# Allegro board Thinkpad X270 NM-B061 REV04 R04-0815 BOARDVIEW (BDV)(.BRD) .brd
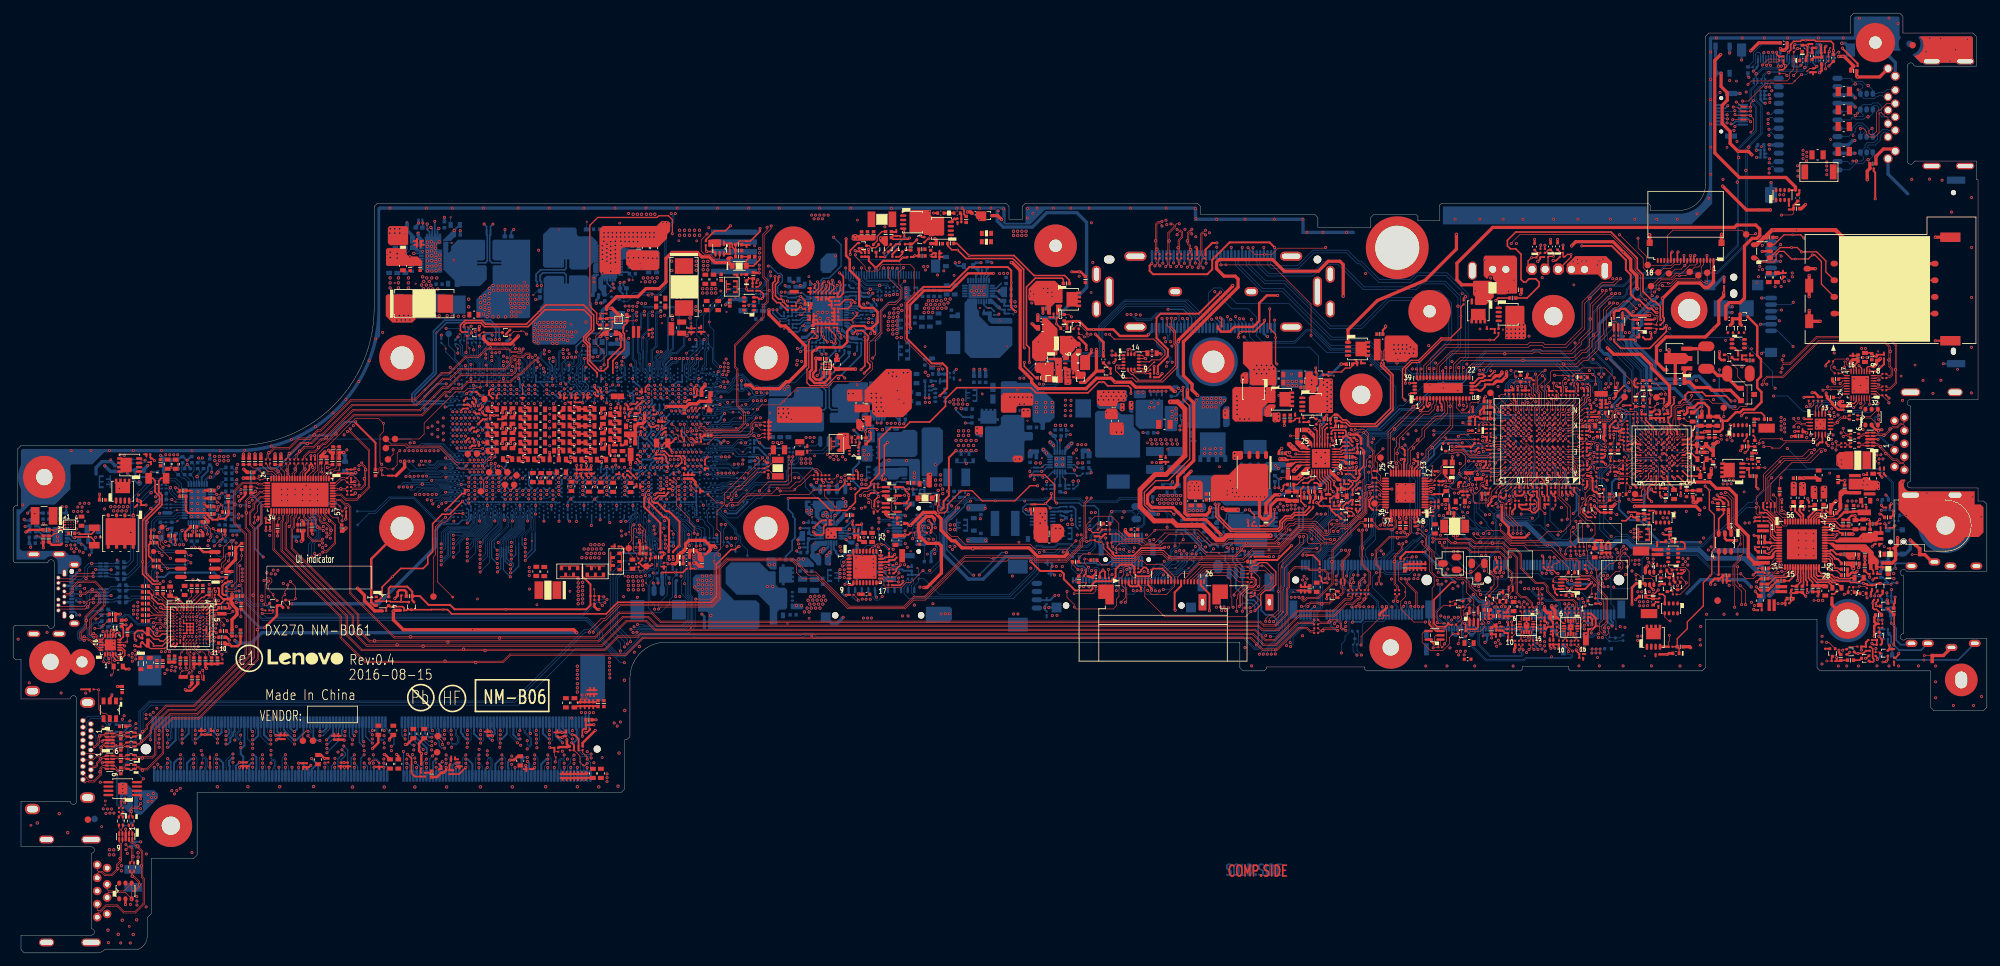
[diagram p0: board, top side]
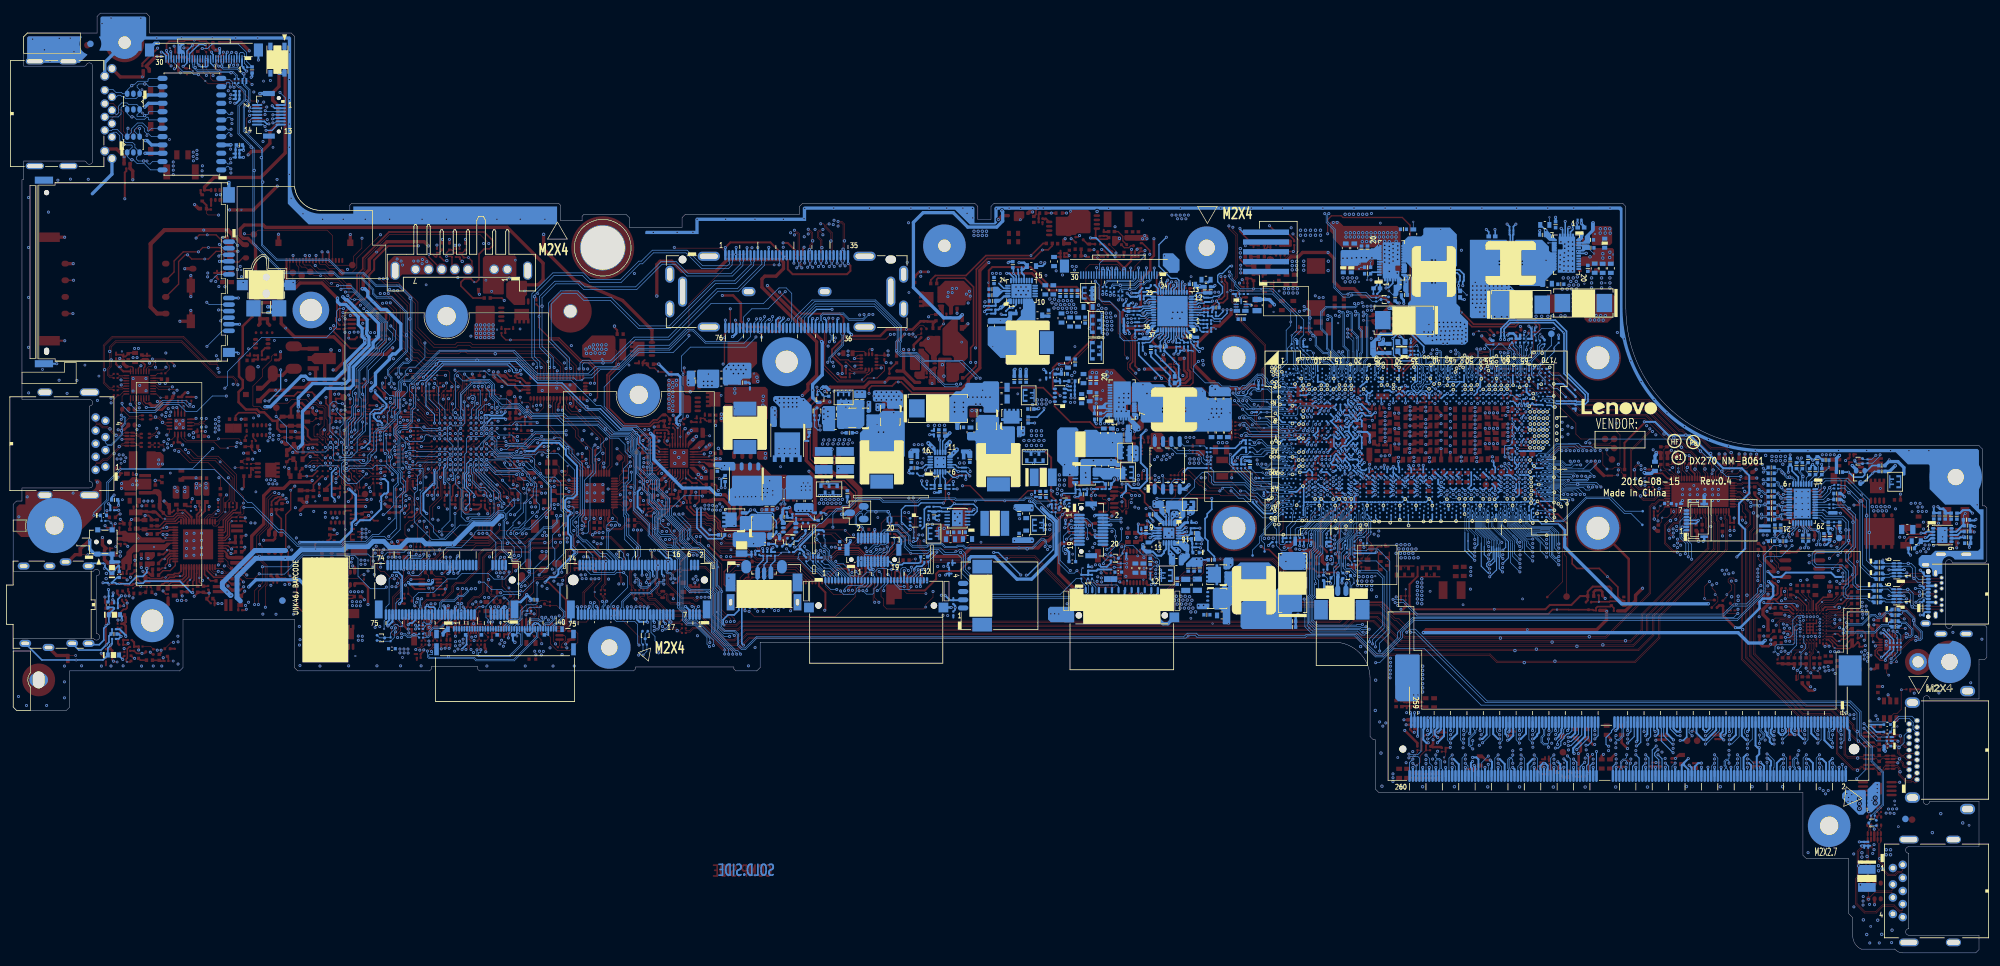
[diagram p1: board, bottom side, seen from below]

Outline 300.95 x 143.41 mm; copper layers: TOP, GND1, IN1, VCC, IN2, IN3, GND2, IN4, GND3, BOTTOM. Coordinates in mm from the lower left corner of the outline.
Outline path: 0,67.91 0,59.81 0.3,59.51 5.28,59.51 arc(5.78,60.01) 6.28,59.51 6.28,50.01 arc(5.78,49.51) 5.28,50.01 0.3,50.01 0,49.71 0,45.1 0.3,44.8 1.2,44.8 1.2,38.75 8.7,38.75 arc(9.2,39.25) 9.7,38.75 9.7,23.15 arc(9.2,22.65) 8.7,23.15 1.2,23.15 1.2,16.2 11.9,16.2 arc(12.4,15.7) 11.9,15.2 11.9,3.7 arc(12.4,3.2) 11.9,2.7 1.2,2.7 1.2,0.5 1.7,0 12.8,0 arc(13.48,0.15) 14.03,0.58 19.17,0.58 arc(20.1,1.39) 20.45,2.58 20.45,5.38 21.05,5.98 21.05,14.41 27.55,14.41 28.05,14.91 28.05,24.51 92.75,24.51 93.25,25.01 93.25,32.51 93.55,32.51 94.05,33.01 94.05,41.91 arc(95.66,45.8) 99.55,47.41 187.05,47.41 187.05,43.53 187.55,43.03 190.75,43.03 191.05,43.33 191.05,43.63 206.05,43.63 206.05,43.33 206.35,43.03 229.85,43.03 230.15,43.33 230.15,43.73 237.15,43.73 237.15,43.33 237.45,43.03 257.55,43.03 258.05,43.53 258.05,50.91 275.05,50.91 275.05,43.53 275.55,43.03 292.35,43.03 292.35,37.48 292.85,36.98 300.45,36.98 300.95,37.48 300.95,48 288.7,48 arc(287.82,47.97) 288.25,48.73 288.25,57.53 arc(287.82,58.29) 288.7,58.26 300.95,58.26 300.95,68.45 300.45,68.95 299.6,68.95 299.6,70.95 289.3,70.95 arc(288.8,71.45) 289.3,71.95 289.3,83.45 arc(288.8,83.95) 289.3,84.45 299.6,84.45 299.6,117.99 299.33,117.99 299.33,120.84 290.07,120.84 arc(289.9,120.79) 289.79,120.65 arc(289.23,120.35) 288.83,120.84 288.83,135.32 arc(289.23,135.81) 289.79,135.51 arc(289.9,135.37) 290.07,135.32 299.33,135.32 299.33,139.87 298.83,140.37 288.15,140.37 288.15,142.91 287.65,143.41 280.65,143.41 280.15,142.91 280.15,140.37 258.55,140.37 258.05,139.87 258.05,117.31 arc(256.88,114.48) 254.05,113.31 249.6,113.31 249.6,114.11 249.3,114.41 217.8,114.41 217.5,114.11 217.5,111.71 214.2,111.71 214.2,112.41 213.9,112.71 207.5,112.71 207,112.21 207,110.71 198.95,110.71 198.95,112.21 198.45,112.71 181.05,112.71 181.05,113.91 180.55,114.41 154.35,114.41 153.85,113.91 153.85,111.91 151.85,111.91 151.85,113.91 151.35,114.41 55.55,114.41 55.05,113.91 55.05,98.41 arc(48.9,83.56) 34.05,77.41 1.2,77.41 0.7,76.91 0.7,68.21 0.3,68.21 0,67.91

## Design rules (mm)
net group -DCIN_PWR_DTCT: nets -DCIN_PWR_DTCT N19402841
net group -SPK_MUTE: nets -SPK_MUTE N40201576
net group BEEP_MIX_ATT: nets BEEP_MIX_ATT N23217805
net group COEX1: nets COEX1 N43583240
net group COEX2: nets COEX2 N43583233
net group COEX3: nets COEX3 N43583220
net group DIFFPAIR0: nets USBP8+_CONN USBP8-_CONN
net group DOCK_I2S_BCLK: nets DOCK_I2S_BCLK N23217894
net group DOCK_I2S_LRCLK: nets DOCK_I2S_LRCLK N23217898
net group DOCK_I2S_SD_O: nets DOCK_I2S_SD_O N23217896
net group DP3: nets DDIP1_CTRLCLK DDIP1_CTRLDATA
net group HP_JACK_IN: nets HP_JACK_IN N40201579
net group M_A_DDRCLK0_1866M: nets -M_A_DDRCLK0_1866M M_A_DDRCLK0_1866M
net group M_A_DDRCLK1_1866M: nets -M_A_DDRCLK1_1866M M_A_DDRCLK1_1866M
net group M_A_DQS8: nets -M_A_DQS8 M_A_DQS8
net group N19352870: nets N19352870 N19353084
net group N19352890: nets N19352890 N19353108
net group PCIE2_TXN: nets PCIE2_TXN PCIE2_TXN_C
net group PCIE2_TXP: nets PCIE2_TXP PCIE2_TXP_C
net group RJ45_ACTIVITY: nets N22083090 RJ45_ACTIVITY
net group RJ45_ACTIVITY_SYS: nets N22083116 RJ45_ACTIVITY_SYS
net group RJ45_LINKUP: nets N22083088 RJ45_LINKUP
net group RJ45_LINKUP_SYS: nets N22083114 RJ45_LINKUP_SYS
net group SPI_CLK_LFT: nets SPI_CLK_LFT SPI_CLK_LFT_R
net group USBC_CC1: nets N46487592 USBC_CC1
net group USBC_CC2: nets N46487596 USBC_CC2
net group USBC_DPAUX: nets USBC_DPAUX1 USBC_DPAUX2
net group -INTRUDER: nets -INTRUDER
net group CARDREADER: nets SD_MMC_CMD
net group CLK(12/15): nets -RTCRST -SRTCRST XCLK_BIASREF
net group DDR_CMD: nets M_A_ALERT_N
net group DOCK_I2S_MCLK: nets DOCK_I2S_MCLK I2S_CTRL N23217875
net group POWER_SEQUENCE(12/12): nets -PCH_SLP_S0 -PCH_SLP_S3 -PCH_SLP_S4 -PCH_SLP_S5 -PLTRST_FAR -PLTRST_NEAR -PROCHOT -PWRSW_EC -PWRSWITCH -RSMRST -XDP_DBR BPWRG CPUCORE_PWRGD MPWRG PECI
net group REFGND: nets -BATLOW -CLKRUN -DOCK_ATTACHED_3M -EC_RESET -EC_SCI -JTAG_RST -LPC_FRAME -PLTRST -PWRSHUTDOWN -SUS_STAT -XDP_PRDY -XDP_PREQ -XDP_TRST CFG3 DMIC_CLK DMIC_DATA DOCK_I2S_SD_I DSWPWROK EC_PWRREQ IRQSER PCH_PWROK PCH_TCK PROCHOT_EC SYS_PWROK UIM_CLK UIM_DATA XDP_TDI XDP_TDO XDP_TMS
net group S25: nets EDP_COMP
net group SVID: nets -SVID_ALERT -SVID_ALERT_R SVID_CLK SVID_DATA
net group USB2(15/15): nets USBCOMP

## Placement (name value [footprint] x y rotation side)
C1  0.01U_0402_25V7K  [C_0402]  140.77 108.22 0 top
C2  0.1U_0201_6.3V6K  [C_0201]  139.66 86.45 180 bottom
C3  1U_0402_10V6K  [C_0402]  140.2 88.35 0 bottom
C4  0.1u_0201_10V6K  [C_0201]  130.48 106.82 270 top
C5  0.01U_0201_10V7K  [C_0201]  129.91 106.82 270 top
C6  0.01U_0402_25V7K  [C_0402]  138.1 107.38 0 top
C7  0.1U_0402_25  [C_0402]  138.13 106.36 0 top
C8  1UF_25V_0603  [C_0603]  142.24 104.8 90 bottom
C9  0.1u_0201_10V6K  [C_0201]  134.81 101.01 90 bottom
C10  0.1u_0201_10V6K  [C_0201]  134.24 101.02 90 bottom
C11  0.1u_0201_10V6K  [C_0201]  133.65 100.87 90 bottom
C12  0.1u_0201_10V6K  [C_0201]  133.07 100.88 90 bottom
C13  0.1u_0201_10V6K  [C_0201]  132.41 100.32 90 bottom
C14  0.1u_0201_10V6K  [C_0201]  131.82 100.31 90 bottom
C19  1000P_0201_25V7K  [C_0201]  143.43 88.48 180 bottom
C20  1000P_0201_25V7K  [C_0201]  269.92 136.8 270 top
C21  1000P_0201_25V7K  [C_0201]  271.5 138.05 270 top
C30  0.1U_0201_6.3V6-K  [C_0201]  281.99 68.11 0 top
C36  0.01U_0201_6.3V7-K  [C_0201]  286.18 67.96 180 top
C73  1U_0402_6.3V6-K  [C_0402]  283.12 65.49 0 top
C75  0.1U_0402_25V6-K  [C_0402]  225.38 49.59 270 top
C76  10U_0603_6.3V6M  [C_0603]  221.3 47.29 0 top
C77  0.01U_0201_10V7K  [C_0201]  234.51 51.91 0 top
C78  0.01U_0201_10V7K  [C_0201]  234.29 47.07 90 top
C79  1U_0402_10V6K  [C_0402]  234.35 51.17 0 top
C83  0.22U_0201_6.3V6-K  [C_0201]  238.69 52.51 270 top
C84  0.22U_0201_6.3V6-K  [C_0201]  236.66 51.93 90 top
C85  0.22U_0201_6.3V6-K  [C_0201]  238.06 52.51 270 top
C86  0.22U_0201_6.3V6-K  [C_0201]  237.3 51.93 90 top
C90  0.01U_0201_10V7K  [C_0201]  227.9 51.96 270 top
C91  0.01U_0201_10V7K  [C_0201]  226.17 49.8 0 top
C92  1U_0402_10V6K  [C_0402]  225.71 51.4 0 top
C97  0.1u_0201_10V6K  [C_0201]  279.35 77.78 180 top
C98  0.1u_0201_10V6K  [C_0201]  279.35 77.19 180 top
C99  0.1u_0201_10V6K  [C_0201]  285.26 73.19 90 top
C100  0.1u_0201_10V6K  [C_0201]  284.63 73.19 90 top
C101  150U_B2_6.3VM_R35M  [C_B2]  282.64 75.2 0 top
C107  4.7U_0402_6.3V6M  [C_0402]  271.81 78.85 0 top
C108  0.1u_0201_10V6K  [C_0201]  272.27 79.59 0 top
C109  4.7U_0402_6.3V6M  [C_0402]  18.73 21.83 180 bottom
C110  0.1u_0201_10V6K  [C_0201]  18.64 23.15 180 bottom
C111  0.1U_0201_6.3V6K  [C_0201]  215.11 83.35 0 top
C112  0.1U_0201_6.3V6K  [C_0201]  217.22 83.35 0 top
C113  0.1U_0201_6.3V6K  [C_0201]  225.01 88.03 180 top
C114  0.1U_0201_6.3V6K  [C_0201]  214.18 75.62 270 top
C115  0.1U_0201_6.3V6K  [C_0201]  212.19 75.94 270 top
C116  1U_0402_6.3V6K  [C_0402]  266.01 123.29 0 bottom
C117  0.1U_0201_6.3V6K  [C_0201]  266.44 121.97 0 bottom
C118  0.1U_0201_6.3V6K  [C_0201]  266.44 131.53 0 bottom
C119  0.1U_0201_6.3V6K  [C_0201]  266.44 121.39 0 bottom
C120  0.1U_0201_6.3V6K  [C_0201]  266.44 122.55 0 bottom
C121  0.1U_0201_6.3V6K  [C_0201]  266.44 130.29 0 bottom
C122  100P_1808_2KV  [C_1808]  273.17 119.18 0 top
C123  0.1U_0201_6.3V6K  [C_0201]  266.44 130.89 0 bottom
C124  4.7U_0402_6.3V6M  [C_0402]  268.3 109.19 180 top
C125  0.1U_0201_6.3V6K  [C_0201]  226.25 59.5 270 top
C126  1U_0402_6.3V6K  [C_0402]  242.19 61.9 270 top
C127  10U_0603_6.3V6M  [C_0603]  241.15 61.75 270 top
C128  0.1U_0201_6.3V6K  [C_0201]  214.11 59.32 270 top
C129  10U_0603_6.3V6M  [C_0603]  198.76 55.09 90 top
C130  1U_0402_6.3V6K  [C_0402]  197.69 55.1 90 top
C131  4.7U_0402_6.3V6M  [C_0402]  277.4 83.83 0 top
C132  0.1U_0201_6.3V6K  [C_0201]  279.08 82.88 90 top
C133  10U_0603_6.3V6M  [C_0603]  267.7 102.36 90 top
C134  10U_0603_6.3V6M  [C_0603]  282.36 91.57 270 top
C135  0.1U_0402_6.3V7-K  [C_0402]  283.4 91.43 270 top
C136  1U_0402_6.3V6K  [C_0402]  278.33 87.55 180 top
C137  0.1U_0201_6.3V6K  [C_0201]  285.61 87.72 180 top
C138  6P_0201_25V8-D  [C_0201]  277.48 90.26 180 top
C139  0.1U_0201_6.3V6K  [C_0201]  285.61 88.36 180 top
C140  4.7U_0402_6.3V6M  [C_0402]  281.31 91.25 270 top
C141  0.1U_0201_6.3V6K  [C_0201]  280.53 91.12 270 top
C142  0.1U_0201_6.3V6K  [C_0201]  284.13 91.01 270 top
C143  0.1u_0201_10V6K  [C_0201]  134.16 66.43 0 top
C144  0.1u_0201_10V6K  [C_0201]  179.75 106.55 270 top
C145  0.1u_0201_10V6K  [C_0201]  179.12 106.55 270 top
C146  0.1u_0201_10V6K  [C_0201]  178.13 106.6 270 top
C147  0.1u_0201_10V6K  [C_0201]  177.49 106.6 270 top
C148  0.1u_0201_10V6K  [C_0201]  176.48 106.6 270 top
C149  0.1u_0201_10V6K  [C_0201]  175.84 106.6 270 top
C150  0.1u_0201_10V6K  [C_0201]  174.83 106.6 270 top
C152  0.1u_0201_10V6K  [C_0201]  174.19 106.6 270 top
C155  220P_0201_25V7K  [C_0201]  225.29 78.75 180 top
C156  220P_0201_25V7K  [C_0201]  223.5 80.59 180 top
C157  4700P_0402_25V  [C_0402]  224.88 70.09 180 top
C158  47P_0201_25V8J  [C_0201]  241.92 69.58 0 top
C159  47P_0201_25V8J  [C_0201]  224.69 72.08 0 top
C160  2200PF_0201_25V  [C_0201]  225.27 77.36 180 top
C161  22P_0201_25V8  [C_0201]  93.13 99.99 270 bottom
C162  2200PF_0201_25V  [C_0201]  225.24 75.6 90 top
C163  22P_0201_25V8  [C_0201]  178.14 81.3 0 bottom
C164  22P_0201_25V8  [C_0201]  17.68 20.94 180 bottom
C165  2200PF_0201_25V  [C_0201]  225.37 73.31 90 top
C166  22P_0201_25V8  [C_0201]  243.39 47.56 90 bottom
C167  22P_0201_25V8  [C_0201]  204.33 47.05 0 bottom
C168  10U_0603_6.3V6M  [C_0603]  242.63 80.45 180 top
C169  0.1U_0201_6.3V6K  [C_0201]  242.82 83.78 180 top
C170  0.1U_0201_6.3V6K  [C_0201]  242.82 84.37 180 top
C171  0.1U_0201_6.3V6K  [C_0201]  242.82 83.22 180 top
C172  4.7U_0402_6.3V6M  [C_0402]  242.5 78.78 180 top
C173  0.1U_0201_6.3V6K  [C_0201]  229.02 68.4 90 top
C174  0.01U_0201_10V7K  [C_0201]  137.02 58.9 270 bottom
C175  220P_0201_25V7K  [C_0201]  128.14 54.65 180 top
C176  22U_0603_6.3V6M  [C_0603]  129.83 59.41 270 bottom
C177  22U_0603_6.3V6M  [C_0603]  128.61 59.41 270 bottom
C178  2.2U_0402_6.3V6M  [C_0402]  171.48 63.74 180 top
C180  1000P_0201_25V7K  [C_0201]  164.91 63.58 270 top
C181  0.1U_0201_6.3V6K  [C_0201]  166.63 63.92 0 top
C184  0.1U_0201_6.3V6K  [C_0201]  168.11 90.59 90 top
C185  10U_0603_6.3V6M  [C_0603]  174.36 91.51 180 top
C186  10U_0603_6.3V6M  [C_0603]  134.53 62.25 90 top
C187  1U_0201_6.3V6  [C_0201]  133.56 59.85 90 top
C188  0.01U_0201_10V7K  [C_0201]  248.52 93.94 180 top
C189  0.01U_0201_10V7K  [C_0201]  251.73 82.19 270 top
C190  1000P_0201_25V7K  [C_0201]  243.43 79.61 0 top
C191  0.01U_0201_10V7K  [C_0201]  250.46 82.19 270 top
C192  1U_0201_6.3V6-K  [C_0201]  251.09 82.19 270 top
C193  0.22U_0201_6.3V6K  [C_0201]  245.59 77.45 0 top
C194  0.1u_0201_10V6K  [C_0201]  254.27 70.88 270 top
C195  0.1u_0201_10V6K  [C_0201]  251.09 70.3 90 top
C196  0.1UF_25V  [C_0402]  256.08 69.64 90 top
C197  0.1U_0402_25V  [C_0402]  257.66 76.38 180 top
C198  1U_0402_10V6K  [C_0402]  249.7 82.52 270 top
C199  470P_0201_25V7K  [C_0201]  257.32 79.4 180 top
C200  2.2UF_0603_25V  [C_0603]  257.32 81.83 270 top
C201  1U_0603_25V7K  [C_0603]  257.13 69.19 90 top
C202  1U_0603_25V7K  [C_0603]  253.25 70.65 270 top
C203  0.1U_0402_25V7K  [C_0402]  254.01 82.48 270 top
C204  1U_0603_25V7K  [C_0603]  258.22 75.34 180 top
C205  0.01U_0402_25V7K  [C_0402]  259.22 77.65 270 top
C206  0.22U_0603_50V7K  [C_0603]  258.65 72.75 180 top
C207  470P_0201_25V7K  [C_0201]  245.47 71.68 0 top
C208  0.1u_0201_10V6K  [C_0201]  252.36 82.28 270 top
C209  0.1U_0402_25V7K  [C_0402]  130.05 77.67 90 top
C211  0.1U_0402_25V7K  [C_0402]  247.74 66.08 90 top
C212  0.1U_0402_25V7K  [C_0402]  265.13 76.26 270 top
C213  0.047U_0402_25V7K  [C_0402]  263.66 77.28 0 top
C215  0.1U_0402_25V7K  [C_0402]  248.01 54.37 0 top
C216  0.1U_0402_25V7K  [C_0402]  252.66 64.71 270 top
C217  0.1U_0201_6.3V6K  [C_0201]  163.26 57.47 0 top
C219  0.1U_0201_6.3V6K  [C_0201]  211.34 54.75 90 top
C220  0.1U_0201_6.3V6K  [C_0201]  210.7 54.75 90 top
C229  0.1U_0402_10V6-K  [C_0402]  16.62 39.74 90 top
C230  0.1u_0201_10V6K  [C_0201]  18.09 16.94 270 bottom
C232  0.1u_0201_10V6K  [C_0201]  18.7 16.94 270 bottom
C234  150U_B2_6.3VM_R35M  [C_B2]  18.3 12.74 90 bottom
C235  0.1u_0201_10V6K  [C_0201]  16.14 21.51 90 top
C236  0.1u_0201_10V6K  [C_0201]  16.72 21.51 90 top
C238  4.7U_0402_6.3V6M  [C_0402]  16.24 34.58 0 top
C241  0.22U_0201_6.3V6-K  [C_0201]  231.81 52.72 270 top
C242  0.22U_0201_6.3V6-K  [C_0201]  231.17 52.72 270 top
C243  0.22U_0201_6.3V6-K  [C_0201]  229.83 52.13 90 top
C244  0.22U_0201_6.3V6-K  [C_0201]  230.44 52.13 90 top
C245  0.1U_0201_6.3V6K  [C_0201]  205.49 54.76 90 top
C246  0.1U_0201_6.3V6K  [C_0201]  204.83 54.76 90 top
C247  0.1U_0201_6.3V6K  [C_0201]  204.25 54.74 90 top
C248  0.1U_0201_6.3V6K  [C_0201]  203.58 54.74 90 top
C249  0.1U_0201_6.3V6K  [C_0201]  198.97 48.83 180 top
C250  0.1U_0201_6.3V6K  [C_0201]  198.97 49.54 180 top
C251  0.1U_0201_6.3V6K  [C_0201]  198.97 50.13 180 top
C252  0.1U_0201_6.3V6K  [C_0201]  198.97 50.84 180 top
C253  0.1U_0201_6.3V6K  [C_0201]  206.07 54.76 90 top
C254  0.1U_0201_6.3V6K  [C_0201]  206.63 54.76 90 top
C255  22P_0201_25V8  [C_0201]  18.2 74.73 90 bottom
C256  0.022U_0402_25V7K  [C_0402]  254.64 46.72 180 top
C257  33P_0201_25V8J  [C_0201]  106.79 62.7 0 bottom
C258  33P_0201_25V8J  [C_0201]  108.34 62.67 0 bottom
C259  33P_0201_25V8J  [C_0201]  246.17 79.95 180 top
C260  4700P_0402_25V  [C_0402]  244.36 85.38 90 top
C261  10U_0603_6.3V6M  [C_0603]  129.75 62.7 90 top
C262  0.1u_0201_10V6K  [C_0201]  128.25 63.72 90 top
C263  0.1u_0201_10V6K  [C_0201]  128.84 63.72 90 top
C264  10U_0603_6.3V6M  [C_0603]  130.97 62.7 90 top
C265  100P_0201_25V8J  [C_0201]  136.34 106.21 0 top
C266  47P_0201_25V8J  [C_0201]  129.34 106.82 270 top
C267  47P_0201_25V8J  [C_0201]  141.25 106.77 180 top
C268  100P_0201_25V8J  [C_0201]  140.66 106.21 0 top
C269  4700P_0402_25V  [C_0402]  264.52 134.28 90 bottom
C271  68P_0201_25V8-J  [C_0201]  226.09 48.62 90 top
C272  100P_0201_25V8J  [C_0201]  234.85 47.65 270 top
C273  100P_0201_25V8J  [C_0201]  227.31 51.37 90 top
C274  100P_0201_25V8J  [C_0201]  275.87 77.91 0 top
C275  100P_0201_25V8J  [C_0201]  18.08 22.57 0 bottom
C277  47P_0201_25V8J  [C_0201]  243.52 61.67 270 top
C278  100P_0201_25V8J  [C_0201]  242.93 61.09 90 top
C279  47P_0201_25V8J  [C_0201]  196.96 55.27 90 top
C280  100P_0201_25V8J  [C_0201]  196.35 55.88 270 top
C281  100P_0201_25V8J  [C_0201]  47.34 68.52 180 bottom
C282  0.1U_0402_25V7K  [C_0402]  112.86 103.82 270 top
C283  0.1U_0402_25V7K  [C_0402]  265.46 81.44 270 top
C284  0.1U_0402_25V7K  [C_0402]  265.77 72.76 180 top
C285  0.1U_0402_25V7K  [C_0402]  109.28 98.72 90 top
C286  22U_0603_6.3V6M  [C_0603]  105.55 103.49 270 top
C287  22U_0603_6.3V6M  [C_0603]  107.5 98.08 90 top
C288  22U_0603_6.3V6M  [C_0603]  105.75 98.08 90 top
C289  22U_0603_6.3V6M  [C_0603]  106.79 103.49 270 top
C290  0.1U_0402_25V7K  [C_0402]  107.96 103.54 270 top
C292  10U_0603_6.3V6M  [C_0603]  125.6 89.1 90 top
C293  0.1U_0402_6.3V7-K  [C_0402]  124.54 88.51 180 top
C294  0.1U_0402_6.3V7-K  [C_0402]  93.58 96.46 90 top
C296  10U_0603_6.3V6M  [C_0603]  91.89 94.58 180 top
C297  1U_0402_6.3V6K  [C_0402]  277.56 84.77 180 top
C298  0.1u_0201_10V6K  [C_0201]  276.24 137.41 180 top
C299  0.01U_0201_10V7-K  [C_0201]  214.74 58.74 90 top
C300  0.01U_0201_10V7-K  [C_0201]  215.33 58.74 90 top
C301  0.1U_0201_6.3V6-K  [C_0201]  226.73 48.62 90 top
C302  0.1U_0402_25V6-K  [C_0402]  221.98 53.89 180 bottom
C303  4.7U_0402_6.3V6M  [C_0402]  212.2 58.28 90 top
C304  0.1U_0201_6.3V6K  [C_0201]  213.52 59.32 270 top
C305  0.01U_0201_6.3V7K  [C_0201]  212.94 59.32 270 top
C306  0.1U_0201_6.3V6-K  [C_0201]  61.57 108.62 0 top
C307  68P_0201_25V8-J  [C_0201]  62.15 108.06 180 top
C308  0.1U_0201_6.3V6-K  [C_0201]  239.39 45.61 180 top
C309  68P_0201_25V8-J  [C_0201]  238.81 45.02 0 top
C310  0.1U_0201_6.3V6-K  [C_0201]  88.58 40.09 270 top
C311  68P_0201_25V8-J  [C_0201]  87.99 39.51 90 top
C312  0.1U_0201_6.3V6K  [C_0201]  32.67 54 270 top
C318  0.1U_0201_6.3V6-K  [C_0201]  282.69 72.95 270 top
C333  10U_0603_6.3V6M  [C_0603]  283.6 73.13 270 top
C417  0.22U_0201_6.3V6-K  [C_0201]  231.76 47.64 270 top
C418  0.22U_0201_6.3V6-K  [C_0201]  231.17 47.64 270 top
C419  0.22U_0201_6.3V6-K  [C_0201]  236.31 47.05 90 top
C420  0.22U_0201_6.3V6-K  [C_0201]  236.94 47.05 90 top
C421  0.22U_0201_6.3V6-K  [C_0201]  238.67 47.64 270 top
C422  0.22U_0201_6.3V6-K  [C_0201]  238.08 47.64 270 top
C500  33P_0201_25V8J  [C_0201]  269.33 136.19 90 top
C502  0.1U_0402_25V6-K  [C_0402]  9.37 64.03 180 top
C535  4.7U_0402_6.3V6M  [C_0402]  267.06 63.51 180 top
C536  0.1U_0402_10V6-K  [C_0402]  267.06 62.62 180 top
C537  4.7U_0402_6.3V6M  [C_0402]  267.45 56.27 270 top
C538  0.1U_0402_10V6-K  [C_0402]  266.53 56.27 270 top
C539  0.1U_0402_10V6-K  [C_0402]  270.01 56.78 180 top
C540  4.7U_0402_6.3V6M  [C_0402]  272.81 55.96 270 top
C541  4.7U_0402_6.3V6M  [C_0402]  275.27 56.02 270 top
C542  0.1U_0402_10V6-K  [C_0402]  274.38 56.02 270 top
C543  2.2U_0402_10V6-K  [C_0402]  278.77 57.64 0 top
C544  2.2U_0402_10V6-K  [C_0402]  278.77 58.53 0 top
C545  4.7U_0402_6.3V6M  [C_0402]  279 65.16 90 top
C546  10U_0603_6.3V6M  [C_0603]  275.29 73.61 270 top
C547  0.1U_0402_10V6-K  [C_0402]  271.46 72.44 0 top
C549  0.1U_0402_10V6-K  [C_0402]  278.27 72.68 270 top
C551  4.7U_0402_6.3V6M  [C_0402]  280.63 67.36 90 top
C552  0.1U_0402_10V6-K  [C_0402]  279.55 67.28 90 top
C553  10U_0603_6.3V6M  [C_0603]  278.6 68.21 180 top
C555  0.1U_0402_10V6-K  [C_0402]  279.26 70.47 90 top
C556  0.1U_0402_10V6-K  [C_0402]  261.65 57.6 180 top
C557  2.2U_0603_6.3V6-K  [C_0603]  278.79 55.71 180 top
C558  1000P_0201_25V7-K  [C_0201]  260.02 57.69 270 top
C559  33P_0402_50V8-J  [C_0402]  280.55 59.42 0 top
C561  33P_0402_50V8-J  [C_0402]  280.49 60.82 0 top
C564  0.1U_0402_25V6-K  [C_0402]  285.12 48.66 0 bottom
C709  0.1U_0402_16V7-K  [C_0402]  60.86 54.45 180 top
C796  10U_0603_10V6-K  [C_0603]  23.94 54.51 90 top
C800  0.1U_0402_25V6-K  [C_0402]  225.23 52.34 180 top
C809  4.7U_0402_6.3V6M  [C_0402]  31.35 47.28 0 top
C810  2.2U_0402_6.3V6-M  [C_0402]  29.93 55.54 270 top
C811  1U_0603_25V6-K  [C_0603]  20.84 45.03 270 top
C812  2.2U_0402_6.3V6-M  [C_0402]  32.29 52.67 180 top
C813  2.2U_0402_6.3V6-M  [C_0402]  19.72 55.08 0 top
C814  10U_0603_10V6-K  [C_0603]  26.15 54.61 90 top
C815  220P_0201_25V7-K  [C_0201]  19.69 49.17 270 top
C816  0.1U_0402_25V  [C_0402]  22.28 58.97 180 top
C817  220P_0201_25V7-K  [C_0201]  19.69 47.4 90 top
C818  0.22U_0402_10V6-K  [C_0402]  24.64 63.67 180 top
C821  .01U_0402_25V7-K  [C_0402]  24.62 45.3 270 top
C822  .01U_0402_25V7-K  [C_0402]  23.76 45.3 270 top
C823  .01U_0402_25V7-K  [C_0402]  22.82 44.61 270 top
C824  .01U_0402_25V7-K  [C_0402]  21.93 44.61 270 top
C830  1U_0402_10V6K  [C_0402]  22.87 55.74 270 top
C852  0.1U_0201_6.3V6K  [C_0201]  162 59.68 180 bottom
C900  1U_0402_6.3V6-K  [C_0402]  16.54 49.85 90 top
C1416  1U_0402_6.3V6-K  [C_0402]  282.33 59.23 270 top
C1417  1000P_0201_25V7-K  [C_0201]  286.79 61.73 180 top
C2503  0.1U_0201_6.3V6-K  [C_0201]  273.54 55.52 90 top
C2522  0.1U_0201_6.3V6-K  [C_0201]  44.76 75.29 270 top
C2523  0.1U_0201_6.3V6-K  [C_0201]  44.13 75.29 270 top
C2524  0.1U_0201_6.3V6-K  [C_0201]  43.49 75.29 270 top
C2525  0.1U_0201_6.3V6-K  [C_0201]  42.86 75.29 270 top
C2526  0.1U_0201_6.3V6-K  [C_0201]  42.22 75.29 270 top
C2527  0.1U_0201_6.3V6-K  [C_0201]  41.59 75.29 270 top
C2528  0.1U_0201_6.3V6-K  [C_0201]  39.18 75.29 270 top
C2529  0.1U_0201_6.3V6-K  [C_0201]  38.54 75.29 270 top
C2530  0.1U_0201_6.3V6-K  [C_0201]  51.53 71.08 180 top
C2531  0.1U_0201_6.3V6-K  [C_0201]  51.53 70.5 180 top
C2543  0.1U_0201_6.3V6-K  [C_0201]  50.86 73.76 270 top
C2544  0.01U_0201_6.3V7-K  [C_0201]  38.54 65.05 90 top
C2545  0.01U_0201_6.3V7-K  [C_0201]  51.5 73.76 270 top
C2546  0.1U_0201_6.3V6-K  [C_0201]  45.4 75.29 270 top
C2571  4.7U_0402_6.3V6M  [C_0402]  271.41 54.06 180 top
C2572  0.1U_0201_6.3V6-K  [C_0201]  270.81 53.35 180 top
C2573  0.1U_0201_6.3V6-K  [C_0201]  266.04 52.29 0 top
C2574  10U_0603_6.3V6M  [C_0603]  266.33 54.48 270 top
C2575  0.01U_0201_6.3V7-K  [C_0201]  284.98 53.36 0 bottom
C2576  0.1U_0201_6.3V6-K  [C_0201]  39.18 65.05 90 top
C2587  2.2U_0402_6.3V6-K  [C_0402]  50.1 64.38 90 top
C2729  680P_0201_25V7-K  [C_0201]  50.77 67.37 180 top
C2730  680P_0201_25V7-K  [C_0201]  50.77 66.74 180 top
C2764  0.22U_0201_6.3V6-K  [C_0201]  239.06 49.44 180 bottom
C2765  0.22U_0201_6.3V6-K  [C_0201]  239.06 50 180 bottom
C8333  1U_0603_25V6-K  [C_0603]  10.42 66.58 270 top
C8337  0.1U_0402_6.3V7-K  [C_0402]  24.84 63.97 270 bottom
C8338  0.1U_0402_6.3V7-K  [C_0402]  23.95 64 270 bottom
C8339  0.1U_0402_6.3V7-K  [C_0402]  29.99 74.47 90 bottom
C8340  0.1U_0402_6.3V7-K  [C_0402]  32.33 65.3 270 bottom
C8341  0.1U_0402_6.3V7-K  [C_0402]  31.44 65.3 270 bottom
C8342  0.1U_0402_6.3V7-K  [C_0402]  33.35 72.28 180 bottom
C8343  0.1U_0402_6.3V7-K  [C_0402]  33.29 67.01 180 bottom
C8344  0.1U_0402_6.3V7-K  [C_0402]  33.29 66.14 180 bottom
C8345  0.1U_0402_6.3V7-K  [C_0402]  28.14 74.8 270 bottom
C8346  0.1U_0402_6.3V7-K  [C_0402]  33.35 71.39 180 bottom
C8347  0.1U_0402_6.3V7-K  [C_0402]  29.03 74.8 270 bottom
C8348  0.1U_0402_6.3V7-K  [C_0402]  33.35 73.19 180 bottom
C8349  0.1U_0402_6.3V7-K  [C_0402]  33.35 74.08 180 bottom
C8350  0.1U_0402_6.3V7-K  [C_0402]  33.32 68.73 180 bottom
C8351  0.1U_0402_6.3V7-K  [C_0402]  33.29 67.87 180 bottom
C8352  0.1U_0402_6.3V7-K  [C_0402]  33.35 70.46 180 bottom
C8353  0.1U_0402_6.3V7-K  [C_0402]  33.35 69.6 180 bottom
C8354  0.1U_0402_6.3V7-K  [C_0402]  28.06 62.84 90 bottom
C8355  0.1U_0402_6.3V7-K  [C_0402]  27.2 62.84 90 bottom
C8356  2.2U_0402_6.3V6-K  [C_0402]  25.17 72.97 90 bottom
C8358  0.1U_0201_6.3V6-K  [C_0201]  24 67.87 180 bottom
C8359  0.1U_0201_6.3V6-K  [C_0201]  24 68.44 180 bottom
C8360  0.1U_0201_6.3V6-K  [C_0201]  23.26 70.85 180 bottom
C8361  0.1U_0201_6.3V6-K  [C_0201]  23.26 71.42 180 bottom
C9112  0.22U_0201_6.3V6-K  [C_0201]  239.04 48.7 180 bottom
C9113  0.22U_0201_6.3V6-K  [C_0201]  239.04 48.12 180 bottom
C9130  0.01U_0201_6.3V7-K  [C_0201]  136.85 68.59 180 top
C9134  33P_0402_50V8-J  [C_0402]  282.34 61.47 270 top
C9135  33P_0402_50V8-J  [C_0402]  283.14 63.72 90 top
C9136  2.2U_0603_6.3V6-K  [C_0603]  280.77 57.24 0 top
C9137  0.1U_0603_6.3V7-K  [C_0603]  282.1 64.74 90 top
C9138  2.2U_0603_6.3V6-K  [C_0603]  280.91 64.64 90 top
C9139  10U_0402_6.3V6-M  [C_0402]  278.98 63.92 0 top
C9140  4.7U_0402_6.3V6M  [C_0402]  271.93 55.96 270 top
C9141  10U_0603_6.3V6M  [C_0603]  281.77 69 0 top
C9142  47P_0402_25V8-J  [C_0402]  266.65 57.12 0 top
C9146  0.1U_0201_6.3V6-K  [C_0201]  271.19 56.01 270 top
C9197  0.1U_0201_6.3V6-K  [C_0201]  243.75 83.26 270 top
C9463  0.1U_0603_50V7-K  [C_0603]  16.73 43.71 180 top
C9464  1U_0201_6.3V6-K  [C_0201]  261.55 67.72 90 top
C9487  0.1U_0402_25V6-K  [C_0402]  272.39 113.58 180 top
CA5  47P_0201_25V8-J  [C_0201]  266.02 58.7 270 top
CA37  0.01U_0201_6.3V7-K  [C_0201]  286.8 44.45 90 top
CA44  1000P_0201_25V7-K  [C_0201]  284.82 59.66 270 bottom
CA45  1000P_0201_25V7-K  [C_0201]  284.98 52.6 0 bottom
CA46  1U_0402_6.3V6-K  [C_0402]  285.93 69.13 180 bottom
CA47  2.2U_0402_6.3V6-K  [C_0402]  286.75 52.59 270 top
CA52  0.01U_0201_6.3V7-K  [C_0201]  286.13 67.55 180 bottom
CA53  220P_0201_25V7-K  [C_0201]  158.3 59.5 180 bottom
CA54  220P_0201_25V7-K  [C_0201]  158.23 58.47 270 bottom
CA55  220P_0201_25V7-K  [C_0201]  157.59 53.24 90 bottom
CA56  220P_0201_25V7-K  [C_0201]  157.59 52.09 270 bottom
CA73  1000P_0201_25V7-K  [C_0201]  284.77 47.03 180 top
CA117  1000P_0201_25V7-K  [C_0201]  272.4 67.6 0 top
CA119  1U_0402_6.3V6-K  [C_0402]  266.13 61.2 0 top
CA122  1000P_0201_25V7-K  [C_0201]  275.84 67.5 0 top
CA124  0.1U_0201_6.3V6-K  [C_0201]  266.24 61.91 0 top
CA127  1000P_0201_25V7-K  [C_0201]  273.82 68.13 90 top
CA142  1000P_0201_25V7-K  [C_0201]  285.05 59.46 270 top
CA243  1000P_0201_25V7-K  [C_0201]  271.7 67.6 180 top
CA913  0.1U_0402_10V6-K  [C_0402]  278.04 67.13 180 top
CC5  47P_0201_25V8-J  [C_0201]  96.43 61.57 270 bottom
CC10  12P_0201_25V8-J  [C_0201]  87.84 91.29 90 bottom
CC11  12P_0201_25V8J  [C_0201]  87.84 93.07 270 bottom
CC12  6.8P_0201_25V8-C  [C_0201]  115.15 73.63 270 top
CC13  6.8P_0201_25V8-C  [C_0201]  115.15 74.22 90 top
CC14  100P_0201_25V8J  [C_0201]  142.58 69.04 270 bottom
CC15  100P_0201_25V8J  [C_0201]  142.58 67.26 90 bottom
CC17  1000P_0201_25V7K  [C_0201]  100.5 60.57 180 bottom
CC18  10U_0603_6.3V6M  [C_0603]  79.77 58.91 270 top
CC19  10U_0603_6.3V6M  [C_0603]  80.98 58.89 270 top
CC20  10U_0603_6.3V6M  [C_0603]  79.26 71.84 90 top
CC21  10U_0603_6.3V6M  [C_0603]  85.12 70.5 90 top
CC22  10U_0603_6.3V6M  [C_0603]  80.5 71.82 90 top
CC23  10U_0603_6.3V6M  [C_0603]  81.75 71.82 90 top
CC24  10U_0603_6.3V6M  [C_0603]  84.29 73.34 180 top
CC25  22U_0603_6.3V6M  [C_0603]  94.14 71.73 270 top
CC26  22U_0603_6.3V6M  [C_0603]  89.6 71.78 270 top
CC27  22U_0603_6.3V6M  [C_0603]  91.47 71.75 270 top
CC28  1U_0201_6.3V6  [C_0201]  96.91 95.06 270 top
CC29  1U_0201_6.3V6  [C_0201]  96.42 85.61 180 top
CC30  1U_0201_6.3V6  [C_0201]  93.3 81.85 0 top
CC31  10U_0603_6.3V6M  [C_0603]  87.79 70.38 90 top
CC32  0.1U_0201_6.3V6K  [C_0201]  92.3 62.01 180 top
CC33  0.1U_0201_6.3V6K  [C_0201]  99.81 74.79 270 top
CC34  0.1U_0201_6.3V6K  [C_0201]  98.03 76.03 270 top
CC35  1U_0201_6.3V6  [C_0201]  102.28 72.37 90 top
CC36  22U_0603_6.3V6M  [C_0603]  99.44 99.86 180 top
CC37  22U_0603_6.3V6M  [C_0603]  99.44 98.64 180 top
CC38  1U_0402_6.3V6K  [C_0402]  112.35 74.99 270 bottom
CC39  22U_0603_6.3V6M  [C_0603]  104.96 85.28 0 top
CC40  22U_0603_6.3V6M  [C_0603]  106.18 82.78 90 top
CC41  1U_0201_6.3V6  [C_0201]  103.18 83.8 90 top
CC42  0.1U_0201_6.3V6K  [C_0201]  104.76 62.74 90 bottom
CC43  1U_0201_6.3V6  [C_0201]  95.04 71.16 0 top
CC44  22U_0603_6.3V6M  [C_0603]  92.39 92.94 270 bottom
CC45  22U_0603_6.3V6M  [C_0603]  91.2 92.94 270 bottom
CC46  22U_0603_6.3V6M  [C_0603]  92.92 75.18 90 top
CC47  22U_0603_6.3V6M  [C_0603]  91.65 75.18 90 top
CC48  22U_0603_6.3V6M  [C_0603]  93.44 77.86 0 top
CC49  22U_0603_6.3V6M  [C_0603]  93.46 80.35 0 top
CC50  1U_0201_6.3V6  [C_0201]  97.65 82.18 90 top
CC51  1U_0201_6.3V6  [C_0201]  104.91 95.35 270 top
CC52  1U_0201_6.3V6  [C_0201]  95.12 75.39 90 top
CC53  1U_0201_6.3V6  [C_0201]  103.54 72.37 90 top
CC54  1U_0201_6.3V6  [C_0201]  98.37 80.47 90 top
CC55  47UF_0805_6.3V  [C_0805]  111.29 99.71 270 bottom
CC56  1U_0201_6.3V6  [C_0201]  98.93 80.47 90 top
CC57  1U_0201_6.3V6  [C_0201]  95.69 79.63 90 top
CC58  1U_0201_6.3V6  [C_0201]  102.42 74.6 270 top
CC59  1U_0201_6.3V6  [C_0201]  102.92 72.37 90 top
CC60  1U_0201_6.3V6  [C_0201]  105.5 74.52 270 top
CC61  1U_0201_6.3V6  [C_0201]  99.58 75.48 180 top
CC62  1U_0201_6.3V6  [C_0201]  121.09 77.22 270 top
CC63  1U_0201_6.3V6  [C_0201]  103.41 95.3 270 top
CC64  47UF_0805_6.3V  [C_0805]  117.62 76.77 180 top
CC65  47UF_0805_6.3V  [C_0805]  119.95 78 270 top
CC66  47UF_0805_6.3V  [C_0805]  101.94 96.27 270 top
CC67  47UF_0805_6.3V  [C_0805]  99.82 77.81 180 top
CC68  0.1U_0201_6.3V6K  [C_0201]  171.55 58.08 180 top
CC69  1U_0402_10V6K  [C_0402]  97.93 60.36 0 top
CC70  1U_0402_10V6K  [C_0402]  96.52 61.83 180 top
CC71  1U_0402_10V6K  [C_0402]  96.49 60.94 180 top
CC72  0.1u_0201_10V6K  [C_0201]  128.24 72.91 0 top
CC73  0.1u_0201_10V6K  [C_0201]  128.83 72.35 180 top
CC74  0.1U_0201_6.3V6K  [C_0201]  285.61 85.86 180 top
CC75  0.1U_0201_6.3V6K  [C_0201]  285.61 86.45 180 top
CC76  0.1U_0201_6.3V6K  [C_0201]  88.63 53.26 90 top
CC78  1U_0201_6.3V6  [C_0201]  86.99 84.77 0 top
CC79  1U_0201_6.3V6  [C_0201]  85.16 84.72 0 top
CC80  1U_0201_6.3V6  [C_0201]  85.65 84.01 180 top
CC81  1U_0201_6.3V6  [C_0201]  85.91 73.74 270 top
CC82  1U_0201_6.3V6  [C_0201]  88.15 73.74 270 top
CC83  1U_0201_6.3V6  [C_0201]  87.44 73.74 270 top
CC84  1U_0201_6.3V6  [C_0201]  86.62 73.74 270 top
CC85  1U_0201_6.3V6  [C_0201]  83.44 84.72 0 top
CC86  1U_0201_6.3V6  [C_0201]  69.33 83.65 270 top
CC87  1U_0201_6.3V6  [C_0201]  70.27 80.14 270 top
CC88  1U_0201_6.3V6  [C_0201]  69.47 78.52 0 top
CC89  1U_0201_6.3V6  [C_0201]  71.02 77.41 180 top
CC90  1U_0201_6.3V6  [C_0201]  72.74 81.42 180 top
CC91  1U_0201_6.3V6  [C_0201]  72.74 82.03 180 top
CC92  1U_0201_6.3V6  [C_0201]  73.92 82.02 270 top
CC93  1U_0201_6.3V6  [C_0201]  92.61 83.12 180 top
CC94  1U_0201_6.3V6  [C_0201]  71.08 82.88 270 top
CC95  1U_0201_6.3V6  [C_0201]  93.21 82.94 0 top
CC96  1U_0201_6.3V6  [C_0201]  92.66 77.46 180 top
CC97  1U_0201_6.3V6  [C_0201]  90.9 77.46 0 top
CC99  0.1U_0201_6.3V6-K  [C_0201]  99.52 80.11 270 top
CD1  10U_0603_6.3V6M  [C_0603]  77.33 28.6 90 top
CD2  10U_0603_6.3V6M  [C_0603]  57.46 28.13 90 top
CD3  10U_0603_6.3V6M  [C_0603]  58.73 28.13 90 top
CD4  10U_0603_6.3V6M  [C_0603]  46.49 28.8 90 top
CD5  10U_0603_6.3V6M  [C_0603]  61.02 34.16 270 top
CD6  10U_0603_6.3V6M  [C_0603]  55.69 34.67 270 top
CD7  10U_0603_6.3V6M  [C_0603]  57.97 34.67 270 top
CD8  10U_0603_6.3V6M  [C_0603]  62.67 34.16 270 top
CD9  10U_0603_6.3V6M  [C_0603]  84.29 37.46 90 top
CD10  10U_0603_6.3V6M  [C_0603]  85.58 37.46 90 top
CD11  1U_0201_6.3V6  [C_0201]  86.5 38.24 270 top
CD12  1U_0201_6.3V6  [C_0201]  87.16 38.25 270 top
CD13  10U_0603_6.3V6M  [C_0603]  89.62 28.09 270 top
CD14  10U_0603_6.3V6M  [C_0603]  88.4 28.09 270 top
CD15  1U_0201_6.3V6  [C_0201]  87.31 26.71 90 top
CD16  1U_0201_6.3V6  [C_0201]  30.16 33.3 90 top
CD17  1U_0201_6.3V6  [C_0201]  48.96 32.54 90 top
CD18  1U_0201_6.3V6  [C_0201]  40.8 32.63 90 top
CD19  1U_0201_6.3V6  [C_0201]  82.99 33.06 90 top
CD20  1U_0201_6.3V6  [C_0201]  49.59 32.54 90 top
CD21  1U_0201_6.3V6  [C_0201]  72.37 33.17 90 top
CD22  1U_0201_6.3V6  [C_0201]  35.04 29.07 270 top
CD23  1U_0201_6.3V6  [C_0201]  44.21 28.94 270 top
CD24  330U_B2_2.5VM_R9M  [C_B2]  82.91 55.36 0 top
CD25  0.1U_0201_6.3V6K  [C_0201]  67.12 27.29 90 top
CD26  0.022U_0201_6.3V  [C_0201]  62.16 27.49 270 top
CD27  2.2U_0402_6.3V6-M  [C_0402]  63.81 27.75 270 top
CD28  0.1U_0201_6.3V6K  [C_0201]  65.29 27.49 90 top
CD29  0.1U_0201_6.3V6K  [C_0201]  48.07 29.66 270 top
CD30  2.2U_0402_6.3V6-M  [C_0402]  87.33 35.57 0 top
CD31  0.1U_0201_6.3V6K  [C_0201]  87.93 34.2 180 top
CD32  0.1U_0201_6.3V6-K  [C_0201]  49.95 28.46 90 top
CD33  68P_0201_25V8-J  [C_0201]  51.04 29.04 270 top
CD34  100P_0201_25V8J  [C_0201]  88.45 37.67 90 top
CD35  47P_0201_25V8J  [C_0201]  87.82 38.25 270 top
CD36  100P_0201_25V8J  [C_0201]  86.72 27.29 270 top
CD37  47P_0201_25V8J  [C_0201]  86.14 26.71 90 top
CD38  1U_0201_6.3V6  [C_0201]  28.69 33.31 90 top
CD39  1U_0201_6.3V6  [C_0201]  44.79 28.94 270 top
CD40  1U_0201_6.3V6  [C_0201]  41.39 32.63 90 top
CD41  1U_0201_6.3V6  [C_0201]  35.62 29.07 270 top
CD42  1U_0201_6.3V6  [C_0201]  30.01 29.06 90 top
CD43  1U_0201_6.3V6  [C_0201]  78.83 28.05 180 top
CD44  1U_0201_6.3V6  [C_0201]  84.31 33.06 90 top
CD45  1U_0201_6.3V6  [C_0201]  68.08 29.04 270 top
CD46  0.1U_0201_6.3V6K  [C_0201]  85.56 26.71 90 top
CD47  0.1U_0201_6.3V6-K  [C_0201]  84.97 26.7 90 top
CD48  0.1U_0201_6.3V6-K  [C_0201]  84.39 26.7 90 top
CD49  0.1U_0201_6.3V6-K  [C_0201]  83.8 26.7 90 top
CD50  1U_0402_6.3V6K  [C_0402]  90.08 38.49 270 top
CD51  10U_0402_6.3V6-M  [C_0402]  89.19 38.49 270 top
CL1  0.1U_0402_16V7-K  [C_0402]  212.34 64.78 90 top
CL2  0.1U_0402_16V7-K  [C_0402]  206.21 66.08 0 top
CL3  0.1U_0402_16V7-K  [C_0402]  206.18 65.19 0 top
CL4  0.1U_0402_16V7-K  [C_0402]  211.47 64.77 90 top
CL5  1U_0402_6.3V6K  [C_0402]  218.77 67.12 0 top
CL6  22U_0603_6.3V6M  [C_0603]  216.8 64.01 90 top
CL7  0.1U_0201_6.3V6K  [C_0201]  210.25 65.28 90 top
CL8  27P_0201_25V8J  [C_0201]  217.93 71.95 270 top
CL9  0.1U_0201_6.3V6K  [C_0201]  213.67 65.1 90 top
CL10  27P_0201_25V8J  [C_0201]  217.33 72.04 180 top
CL11  0.1U_0201_6.3V6K  [C_0201]  220.98 70.42 270 top
CL12  0.1U_0201_6.3V6K  [C_0201]  221.76 70.42 270 top
CL13  22U_0603_6.3V6M  [C_0603]  218.49 70.49 270 top
CL14  0.1U_0201_6.3V6K  [C_0201]  219.55 67.88 180 top
CL16  0.1u_0201_10V6K  [C_0201]  281.24 135.32 180 top
CL17  0.1u_0201_10V6K  [C_0201]  283.69 119.7 180 top
CW1  0.1U_0201_6.3V6K  [C_0201]  269.86 103.17 90 top
CW2  10U_0603_6.3V6M  [C_0603]  268.94 102.36 90 top
D1  -  [RB521CS-30GT2RA_VMN2-2]  139.02 87.26 0 bottom
D2  -  [RB521CS-30GT2RA_VMN2-2]  272.8 137.57 90 top
D13  IP4223CZ6 SO-6 ESD  [AOZ8904CIL_SOT23-6]  282.42 80.56 0 top
D15  AZ1043-04F.R7G_DFN2510P10E10-9  [AZ1043-04FPR7G_DFN2510P10E10]  283.6 77.39 90 top
D16  -  [RB521CS-30GT2RA_VMN2-2]  272.42 136.21 0 top
D17  -  [RCLAMP0502BPTCT_SC75-3]  227.16 55.04 0 top
D18  FTZ6.8EGT148_SC-74A5  [FTZ6P8EGT148_SC-74A5]  265.46 106.06 270 top
D19  -  [RCLAMP0502BPTCT_SC75-3]  200.5 54.7 90 top
D22  -  [RB521CS-30GT2RA_VMN2-2]  160.25 96.46 90 top
D24  RSB5.6SGTE61_SC-79-2-2  [RSB5P6SGTE61_SC-79-2-2]  285.32 60.85 0 top
D25  -  [DAN222MGT2L_VMD3]  162.08 96.38 0 top
D26  -  [DF2S6P8UFS_1-1L1A2]  223.5 79.7 180 top
D28  -  [RB521CS-30GT2RA_VMN2-2]  229.85 88.12 270 top
D29  RB521CM_30  [RB521CS-30GT2RA_VMN2-2]  238.1 58.06 180 top
D30  RB521CM_30  [RB521CS-30GT2RA_VMN2-2]  237.72 54.58 180 top
D31  1SS400CMT2R_VMN2-2  [1SS400CST2RA_VMN2-2]  166.28 65.52 0 top
D34  -  [RB521CS-30GT2RA_VMN2-2]  243.6 76.72 90 top
D35  1SS400CMT2R_VMN2-2  [1SS400CST2RA_VMN2-2]  244.74 76.72 90 top
D36  -  [RB521CS-30GT2RA_VMN2-2]  255.16 70.56 270 top
D37  -  [RB521CS-30GT2RA_VMN2-2]  251.98 69.93 90 top
D38  -  [RB521CS-30GT2RA_VMN2-2]  259.22 74.94 90 top
D39  -  [RB521CS-30GT2RA_VMN2-2]  256.87 73.89 0 top
D41  -  [RB521CS-30GT2RA_VMN2-2]  128.82 78.67 180 top
D42  -  [RB521CS-30GT2RA_VMN2-2]  248.68 67.04 270 top
D43  -  [RB521CS-30GT2RA_VMN2-2]  265.57 77.24 90 top
D44  -  [RB521CS-30GT2RA_VMN2-2]  266.1 74.99 270 top
D46  -  [RB521CS-30GT2RA_VMN2-2]  250.06 54.04 270 top
D47  -  [RB521CS-30GT2RA_VMN2-2]  252.95 62.81 180 top
D51  AZ1043-04F.R7G_DFN2510P10E10-9  [AZ1043-04FPR7G_DFN2510P10E10]  14.3 33.49 270 top
D52  AZ1043-04F.R7G_DFN2510P10E10-9  [AZ1043-04FPR7G_DFN2510P10E10]  14.3 30.09 270 top
D53  AZ1043-04F.R7G_DFN2510P10E10-9  [AZ1043-04FPR7G_DFN2510P10E10]  18.17 18.19 180 top
D54  IP4223CZ6 SO-6 ESD  [AOZ8904CIL_SOT23-6]  16.18 8.25 0 top
D55  -  [DF2S6P8UFS_1-1L1A2]  14.7 33.72 0 bottom
D56  -  [DF2S6P8UFS_1-1L1A2]  14.67 31.56 0 bottom
D57  -  [DF2S6P8UFS_1-1L1A2]  14.7 34.84 0 bottom
D58  -  [RB521CS-30GT2RA_VMN2-2]  254.02 45.71 180 top
D59  RB521CM_30  [RB521CS-30GT2RA_VMN2-2]  248.57 84.37 270 top
D60  RB521CM_30  [RB521CS-30GT2RA_VMN2-2]  247.41 84.34 270 top
D61  -  [RB521CS-30GT2RA_VMN2-2]  111.82 102.58 90 top
D62  RB521CM_30  [RB521CS-30GT2RA_VMN2-2]  89.52 95.83 90 top
D63  RB521CM_30  [RB521CS-30GT2RA_VMN2-2]  90.53 95.83 90 top
D64  RB521CM_30  [RB521CS-30GT2RA_VMN2-2]  249.56 86.4 90 top
D65  RB521CM_30  [RB521CS-30GT2RA_VMN2-2]  248.52 86.4 90 top
D70  -  [EDZVT2R15B_EMD2-2]  19.47 44.98 270 top
D87  AZ1043-04F.R7G_DFN2510P10E10-9  [AZ1043-04FPR7G_DFN2510P10E10]  13.33 53.5 90 bottom
D88  AZ1043-04F.R7G_DFN2510P10E10-9  [AZ1043-04FPR7G_DFN2510P10E10]  13.3 57.46 90 bottom
D94  RSB5.6SGTE61_SC-79-2-2  [RSB5P6SGTE61_SC-79-2-2]  286.35 51.6 180 bottom
D99  RSB5.6SGTE61_SC-79-2-2  [RSB5P6SGTE61_SC-79-2-2]  285.89 57.94 90 bottom
D253  -  [DAN222MGT2L_VMD3]  284.69 45.74 90 top
D705  RB521CM-30T2R_VMN2M  [RB521CS-30GT2RA_VMN2-2]  251.22 57.22 90 top
D707  -  [1SS400CMT2R_VMN2M2]  160.22 95.32 270 top
D708  RB521CM-30T2R_VMN2M  [RB521CS-30GT2RA_VMN2-2]  242.75 82.44 180 top
D709  RB521CM-30T2R_VMN2M  [RB521CS-30GT2RA_VMN2-2]  239.08 87.85 0 top
D710  RSB5.6SGTE61_SC-79-2-2  [RSB5P6SGTE61_SC-79-2-2]  286.5 45.46 180 bottom
D711  -  [PESD5V0U2BT_SOT23-3]  173.34 67.17 270 bottom
D714  RB521CM_30  [RB521CS-30GT2RA_VMN2-2]  244.97 69.96 0 top
D739  RB521CM-30T2R_VMN2M  [RB521CS-30GT2RA_VMN2-2]  280.74 55.03 180 top
D740  RB521CM-30T2R_VMN2M  [RB521CS-30GT2RA_VMN2-2]  281.59 54.86 0 top
D744  RB521CM-30T2R_VMN2M  [RB521CS-30GT2RA_VMN2-2]  272.11 114.73 90 top
DA5  RSB5.6SGTE61_SC-79-2-2  [RSB5P6SGTE61_SC-79-2-2]  285.94 57.79 90 top
DC1  DIO PMEG4002EL SOD882, A.1  [RB521CS-30GT2RA_VMN2-2]  287.66 66.76 180 bottom
DC2  -  [RB520CS-30GT2RA_VMN2-2]  102.19 60.41 0 top
DC3  -  [RB520CS-30GT2RA_VMN2-2]  102.2 59.42 0 top
DC4  -  [RB520CS-30GT2RA_VMN2-2]  127.44 72.45 270 top
DC5  -  [RB520CS-30GT2RA_VMN2-2]  103.25 61.39 180 top
DL1  SRV05-4HTG SOT23-6 ESD  [CM1293A-04SO_SC-74-6]  281.66 131.11 0 bottom
DL2  SRV05-4HTG SOT23-6 ESD  [CM1293A-04SO_SC-74-6]  283.56 122.16 180 bottom
E_L1  EXC24CH900U_4P  [PANAS_EXC24CH900U_4P]  279.99 82.02 270 top
E_L2  EXC24CH900U_4P  [PANAS_EXC24CH900U_4P]  280.16 79.21 270 top
E_L3  EXC24CH900U_4P  [PANAS_EXC24CH900U_4P]  280.16 77.82 270 top
E_L7  EXC24CH900U_4P  [PANAS_EXC24CH900U_4P]  16.73 20.74 180 top
E_L8  EXC24CH900U_4P  [PANAS_EXC24CH900U_4P]  18.23 20.74 180 top
E_L9  EXC24CH900U_4P  [PANAS_EXC24CH900U_4P]  18.42 13.73 180 top
F1  3A_32V_ERBRD3R00X  [F_ERBRD0R50X]  139.9 108.25 270 top
F2  3A_32V_ERBRD3R00X  [F_ERBRD0R50X]  142.07 88.32 270 bottom
F3  0.5A_32V_ERBRD0R50X  [F_ERBRD0R50X]  270.49 138.88 180 top
F4  0.5A_32V_ERBRD0R50X  [F_ERBRD0R50X]  277.56 137.1 270 top
F5  2A_32V_ERBRD2R00X  [F_ERBRD2R00X]  275.74 136.67 270 top
F6  2A_32V_ERBRD2R00X  [F_ERBRD2R00X]  274.3 136.33 90 top
F7  3A_32V_ERBRD3R00X  [F_ERBRD0R50X]  222.29 44.82 180 top
F8  0.5A_32V_ERBRD0R50X  [F_ERBRD0R50X]  134.88 65.54 0 top
F9  0.5A_32V_ERBRD0R50X  [F_ERBRD0R50X]  164.65 57.34 0 top
F10  1A_32V_ERBRD1R00X  [F_ERBRD1R00X]  131.92 58.11 0 bottom
F11  1A_32V_ERBRD1R00X  [F_ERBRD1R00X]  129.6 54.72 0 top
F14  0.5A_32V_ERBRD0R50X  [F_ERBRD0R50X]  162.57 60.44 180 bottom
F15  0.5A_32V_ERBRD0R50X  [F_ERBRD0R50X]  138.18 62.34 90 top
F16  2A_32V_ERBRD2R00X  [F_ERBRD2R00X]  48.11 68.57 0 bottom
F40  0.5A_32V_ERBRD0R50X  [F_ERBRD0R50X]  138.93 59.71 0 bottom
F41  3A_32V_ERBRD3R00X  [F_ERBRD3R00X]  242.68 46.42 0 bottom
F42  0.5A_32V_ERBRD0R50X  [F_ERBRD0R50X]  174.91 62.75 270 bottom
F152  0.5A_32V_ERBRD0R50X  [F_ERBRD0R50X]  171.49 64.63 180 top
FD1  CF  [FIDUCIAL_C40M80]  289.62 138.52 0 top
FD2  CF  [FIDUCIAL_C40M80]  259.89 53.76 0 top
FD3  CF  [FIDUCIAL_C40M80]  289.16 138.72 180 bottom
FD4  CF  [FIDUCIAL_C40M80]  11.41 20.34 0 top
FD5  CF  [FIDUCIAL_C40M80]  259.89 53.76 180 bottom
FD6  CF  [FIDUCIAL_C40M80]  12.42 20.44 180 bottom
FL3  MMZ1005Y152CT_2P  [TDK_MMZ1005Y152CT_2P]  284.77 57.3 90 bottom
FL5  MMZ1005Y152CT_2P  [TDK_MMZ1005Y152CT_2P]  286.49 53.55 270 bottom
FL6  4.7UH_FLF3215T-4R7M_20%  [TDK_FLF3215T-4R7M_2P]  221.4 65.11 180 top
H1  HOLEA  [PAD_CT7P0B6P5D3P5]  114.8 90.81 0 top
H2  HOLEA  [PAD_CT7P0B6P5D3P5]  59.3 90.81 0 top
H3  HOLEA  [PAD_CT7P0B6P5D3P5]  59.3 64.81 0 top
H4  HOLEA  [PAD_CT7P0B6P5D3P5]  114.8 64.81 0 top
H5  HOLEA  [PAD_C6P5D2P8]  24.05 19.41 0 top
H6  HOLEA  [PAD_CT6P5D1P9]  215.98 97.91 0 top
H7  HOLEA  [PAD_CT9P6D6P7]  211.05 107.61 0 top
H8  HOLEA  [PAD_CT7P0B8P4D2P8]  294.65 65.21 0 top
H9  HOLEA  [PAD_CT6P0B5P0D1P9]  283.95 138.91 0 top
H10  HOLEA  [PAD_C6P5D2P5]  210.05 46.61 0 top
H11  HOLEA  [PAD_C6P5D2P5]  118.95 107.61 0 top
H12  HOLEA  [PAD_C6P5D1P9]  158.95 107.91 0 top
H13  HOLEA  [PAD_CT5P0D1P8X2P6]  297.05 41.66 90 top
H14  HOLEA  [PAD_CT6P5B8P0D2P5]  4.75 72.61 0 top
H15  HOLEA  [PAD_CT4P0B2P7D1P7]  10.5 44.41 0 top
H16  HOLEA  [PAD_C6P5D2P5]  5.7 44.41 0 top
J1  I-PEX_20525-040E-02  [I-PEX_20525-040E-02_40P]  233.75 49.45 0 bottom
J3  SINGA_2RJ3047-108411F  [SINGA_2RJ3047-108411F_12P]  285.88 124.51 270 bottom
J4  TYCO_2041180-4  [TYCO_2041180-4_4P-T]  156.1 52.64 270 bottom
J5  HRS_DF12L3P014DP0P5V86A  [HRS_DF12L3P014DP0P5V86A_14P-T]  260.14 129.39 270 bottom
J8  MOLEX_52435-2671  [MOLEX_52435-2671_26P-T]  169.08 56.62 180 top
J10  I-PEX_20374-030E-31  [I-PEX_20374-030E-31_30P]  126.55 103.44 0 bottom
J11  I-PEX_20374-030E-31  [I-PEX_20374-030E-31_30P]  266.05 136.41 0 bottom
J12  TE_2041180-2  [TE_2041180-2_2P-T]  98.98 55.26 0 bottom
J15  HIGHS_FC5AF071-3151H  [HIGHS_FC5AF071-3151H_7P]  45.8 64.51 90 bottom
J16  HIGHS_BT5P0201-1001H  [HIGHS_BT5P0201-1001H_20P-T]  172.1 59.71 0 bottom
J17  TE_2129525-2  [TE_2129525-2_70P]  192.35 106.46 180 bottom
J19  SINGA_2SJ3052-012111F  [SINGA_2SJ3052-012111F_6P]  289.45 59.04 90 bottom
J21  FOX_AS0A826-H4RB-7H  [FOX_AS0A826-H4RB-7H_260P-T]  21.28 35.21 180 bottom
J22  TYCO_2199230-3  [TE_2-2199119-2_75P-T]  225.6 51.64 0 bottom
J23  ALPS_SCDAAA0604  [ALPS_SCDAAA0900_12P]  268.04 107.53 270 bottom
J25  JAE_SF11V006S4C  [JAE_SF11V006S4C_9P-T]  277.68 97.56 90 top
J26  HIGHS_BT5P0201-1001H  [HIGHS_BT5P0201-1001H_20P-T]  138.38 66.81 90 bottom
J32  TYCO_2199230-8  [TE_2-2199119-3_75P-T]  196.3 51.63 0 bottom
J34  SINGA_2UB3908-000101F  [SINGA_2UB3908-000101F_9P]  286.87 74.21 270 bottom
J37  JAE_FL10S012HA1_12P-T  [JAE_FL10F012HA1R3000_12P-T]  137.4 55.36 0 bottom
J38  JAE_FL10F032HA2R3000  [JAE_FL10F032HA2R3000_32P]  177.1 56.86 180 bottom
J41  FCI_10051922-1810ELF  [FCI_10051922-1810ELF_18P-T]  259.26 105.66 0 top
J42  SINGA_2UB3908-000101F  [SINGA_2UB3908-000101F_9P]  14.33 12.95 90 bottom
J43  FOX_QJ111A1-R000H1-7H  [FOX_QJ111A1-R000H1-7H_19P-TXX]  10.65 26.45 270 bottom
JTYC1  HIGHS_UB11126-A5A0B-1H  [HIGHS_UB11126-A5A0B-1H_24P-T]  8.93 52.01 90 bottom
L7  EXC24CH900U_4P  [PANAS_EXC24CH900U_4P]  18.6 33.02 90 top
L8  EXC24CH900U_4P  [PANAS_EXC24CH900U_4P]  18.61 29.59 90 top
L9  EXC24CH900U_4P  [PANAS_EXC24CH900U_4P]  18.6 31.52 90 top
L10  EXC24CH900U_4P  [PANAS_EXC24CH900U_4P]  18.61 28.09 90 top
L12  EXC24CH900U_4P  [PANAS_EXC24CH900U_4P]  17.34 55.98 270 bottom
L13  EXC24CH900U_4P  [PANAS_EXC24CH900U_4P]  17.04 57.78 270 bottom
L14  EXC24CH900U_4P  [PANAS_EXC24CH900U_4P]  17.36 54.22 270 bottom
L15  EXC24CH900U_4P  [PANAS_EXC24CH900U_4P]  17.04 59.51 270 bottom
L16  EXC24CH900U_4P  [PANAS_EXC24CH900U_4P]  14.64 50.48 270 bottom
L17  EXC24CH900U_4P  [PANAS_EXC24CH900U_4P]  14.61 52.26 270 bottom
LA11  BLM18PG221SN1D_2P  [MURAT_BLM18PG221SN1D_2P]  272.7 68.81 90 top
LA12  BLM18PG221SN1D_2P  [MURAT_BLM18PG221SN1D_2P]  271.48 68.81 90 top
LA13  BLM18PG221SN1D_2P  [MURAT_BLM18PG221SN1D_2P]  274.71 68.37 90 top
LA14  BLM18PG221SN1D_2P  [MURAT_BLM18PG221SN1D_2P]  276.06 68.4 90 top
NOREF  -  []  34.81 49.29 0 top
NOREF#2  -  []  38.8 44.02 0 top
NOREF#3  -  []  168.79 3.62 0 top
NOREF#4  -  []  38.69 59.01 0 top
NOREF#5  -  []  71.51 38.11 0 top
NOREF#6  -  []  37.52 35.5 0 top
NOREF#7  -  []  -44.82 45.2 180 bottom
NOREF#8  -  []  45.66 85.68 180 bottom
NOREF#9  -  []  62.95 84.5 180 bottom
PC3  0.01U_0402_25V7K  [C_0402]  157.02 98.34 0 top
PC4  0.1U_0402_25V7K  [C_0402]  163.5 103.22 270 top
PC5  100P_0201_25V8-J  [C_0201]  111.82 108.61 270 top
PC6  1000P_0402_25V7-K  [C_0402]  131.2 110.04 270 top
PC7  0.01U_0402_25V7-K  [C_0402]  129.37 110.04 270 top
PC8  0.01U_0402_25V7-K  [C_0402]  130.26 110.04 270 top
PC9  1000P_0402_25V7-K  [C_0402]  133.03 109.16 90 top
PC10  0.47U_0402_25V6-K  [C_0402]  133.92 109.16 90 top
PC11  0.01U_0402_25V7K  [C_0402]  145.32 112.39 270 top
PC13  1U_0402_25V6-K  [C_0402]  13.18 69.12 0 top
PC14  10U_0603_25V6-M  [C_0603]  23.56 73.87 90 top
PC15  10U_0603_25V6-M  [C_0603]  24.78 73.87 90 top
PC16  0.01U_0402_25V7K  [C_0402]  22.47 75.26 270 top
PC17  680P_0402_50V7-K  [C_0402]  110.17 108.09 0 top
PC18  390P_0201_25V7-K  [C_0201]  185.38 61.19 270 bottom
PC19  2200P_0201_25V7K  [C_0201]  184.79 61.19 270 bottom
PC20  390P_0201_25V7-K  [C_0201]  187.18 61.34 270 bottom
PC21  2200P_0201_25V7K  [C_0201]  187.78 60.77 0 bottom
PC22  390P_0201_25V7-K  [C_0201]  233.45 106.18 0 top
PC23  2200P_0201_25V7K  [C_0201]  235.87 106.24 0 top
PC24  390P_0201_25V7-K  [C_0201]  232.84 106.11 180 top
PC25  2200P_0402_25V7-K  [C_0402]  229.98 101.21 180 top
PC26  0.01U_0402_25V7K  [C_0402]  182.94 66.53 0 bottom
PC27  0.01U_0402_25V7K  [C_0402]  264.36 90.42 0 top
PC28  0.1U_0402_6.3V7-K  [C_0402]  110.17 107.17 0 top
PC50  4.7U_0603_25V6-M  [C_0603]  157.68 95.37 180 top
PC51  1U_0402_25V6-K  [C_0402]  157.09 87.74 180 top
PC52  22P_0201_25V8-J  [C_0201]  161.65 88.43 180 top
PC53  4.7U_0603_25V6-M  [C_0603]  161.67 90.62 0 top
PC54  4.7U_0603_25V6-M  [C_0603]  161.67 89.4 0 top
PC80  15U_B2_25V  [C_B2]  6.1 66.69 0 top
PC81  10U_0805_25V6-K  [C_0805]  11.29 64.61 0 bottom
PC82  0.01U_0603_50V  [C_0603]  10.07 62.83 0 bottom
PC83  0.47U_0402_25V6-K  [C_0402]  8.1 66.21 90 bottom
PC84  0.1U_0402_25V6  [C_0402]  3.38 62.53 180 bottom
PC102  1U_0402_25V6-K  [C_0402]  195.26 71.47 180 top
PC128  47P_0201_25V8-J  [C_0201]  204.75 68.39 180 top
PC129  2200P_0402_25V7-K  [C_0402]  193.84 82.05 270 top
PC131  100P_0201_50V7-K  [C_0201]  205.13 72.5 180 top
PC132  10U_0603_25V6-K  [C_0603]  193.67 88.25 180 bottom
PC133  100P_0201_25V8-J  [C_0201]  202.98 77.93 270 top
PC134  1U_0402_25V6-K  [C_0402]  207.93 94.42 0 top
PC135  10U_0603_25V6-K  [C_0603]  196.28 88.25 0 bottom
PC136  0.01U_0402_25V7-K  [C_0402]  185.15 68.54 270 bottom
PC137  15P_0201_25V8-J  [C_0201]  201.6 78.76 0 top
PC138  10U_0603_25V6-M  [C_0603]  179.64 69.67 270 bottom
PC139  100P_0201_50V7-K  [C_0201]  202.38 71.55 0 top
PC140  0.1U_0402_25V6-K  [C_0402]  196.37 86.29 0 top
PC141  0.1U_0402_25V7K  [C_0402]  201.69 82.1 270 top
PC142  330P_0201_25V7-K  [C_0201]  179.71 78.13 90 bottom
PC143  330P_0201_25V7-K  [C_0201]  188.6 86.28 90 bottom
PC144  1U_0402_25V6-K  [C_0402]  199.32 71.34 270 top
PC145  0.1U_0402_25V7K  [C_0402]  197.51 70.4 0 top
PC146  1000P_0402_25V7-K  [C_0402]  182.84 69.15 180 top
PC147  0.047U_0402_25V7K  [C_0402]  194.31 72.51 0 top
PC148  1800P_0201_25V7-K  [C_0201]  204.23 78 270 top
PC149  10U_0603_25V6-M  [C_0603]  180.91 69.67 270 bottom
PC150  10U_0603_25V6-K  [C_0603]  193.67 87.03 180 bottom
PC151  10U_0603_25V6-M  [C_0603]  179.64 69.67 270 top
PC152  100P_0201_50V7-K  [C_0201]  205.28 73.62 180 top
PC153  0.1U_0402_25V7K  [C_0402]  201.66 80.35 0 top
PC154  0.1U_0402_25V7K  [C_0402]  200.82 81.42 180 top
PC155  2.2U_0402_10V6-K  [C_0402]  193.94 76.24 180 top
PC156  10U_0603_25V6-K  [C_0603]  193.67 87.03 180 top
PC157  680P_0201_25V7-K  [C_0201]  202.78 79.35 270 top
PC158  0.1U_0402_25V7K  [C_0402]  197.77 69.46 180 top
PC159  0.01U_0201_25V6-K  [C_0201]  205.53 89.98 180 top
PC160  10U_0603_25V6-K  [C_0603]  193.67 88.25 180 top
PC161  10U_0603_25V6-K  [C_0603]  196.28 88.25 0 top
PC162  0.047U_0402_25V7K  [C_0402]  195.82 79.79 0 top
PC163  10U_0603_25V6-M  [C_0603]  180.91 69.67 270 top
PC164  0.1U_0402_25V7K  [C_0402]  198.6 69.46 0 top
PC165  1U_0402_25V6-K  [C_0402]  202 70.76 0 top
PC166  0.1U_0402_25V7K  [C_0402]  205.01 76.34 0 top
PC167  0.01U_0402_25V7-K  [C_0402]  199.27 86.02 180 top
PC170  1U_0402_25V6-K  [C_0402]  194.72 81.16 90 top
PC180  100P_0402_50V8-J  [C_0402]  186.06 68.54 270 bottom
PC181  47P_0402_50V8-J  [C_0402]  182.84 70.04 180 top
PC182  100P_0402_50V8-J  [C_0402]  196.4 87.18 0 bottom
PC183  47P_0402_50V8-J  [C_0402]  196.4 87.18 0 top
PC203  10U_0805_25V6K  [C_0805]  174.7 80.66 0 bottom
PC204  10U_0805_25V6K  [C_0805]  174.7 80.66 0 top
PC205  0.1U_0402_25V6-K  [C_0402]  171.46 84.01 90 bottom
PC206  0.1U_0402_25V6-K  [C_0402]  147.38 87.08 90 bottom
PC207  47P_0402_50V8-J  [C_0402]  146.24 82.99 180 bottom
PC208  10U_0805_25V6K  [C_0805]  149.39 84.52 0 bottom
PC209  10U_0805_25V6K  [C_0805]  149.4 86.3 0 bottom
PC210  0.1U_0402_25V6-K  [C_0402]  173.75 70.52 270 bottom
PC211  0.01U_0402_25V  [C_0402]  158.89 78.88 90 bottom
PC212  4.7U_0402_6.3V  [C_0402]  159.8 78.9 90 bottom
PC213  4.7U_0402_6.3V  [C_0402]  159.62 71.31 270 bottom
PC214  0.1U_0402_25V7-K  [C_0402]  163.99 74.87 90 bottom
PC215  0.1U_0402_25V7-K  [C_0402]  155.08 75.78 270 bottom
PC216  680P_0402_50V7K  [C_0402]  167.8 82.82 90 top
PC217  680P_0402_50V7K  [C_0402]  156.04 80.2 0 bottom
PC218  0.01U_0201_6.3V7-K  [C_0201]  145.14 70.18 270 bottom
PC219  47P_0402_50V8-J  [C_0402]  174.96 83.07 0 bottom
PC220  220U_B2_6.3VM_R35M  [C_B2]  145.25 72.58 0 bottom
PC221  68P_0402_50V8J  [C_0402]  148.29 87.06 90 bottom
PC222  220U_B2_6.3VM_R35M  [C_B2]  174.1 73.77 270 bottom
PC223  220U_B2_6.3VM_R35M  [C_B2]  177.35 73.77 270 bottom
PC224  0.01U_0201_6.3V7-K  [C_0201]  175.73 74.93 90 top
PC225  0.1U_0201_6.3V6K  [C_0201]  160.54 79.68 270 bottom
PC226  68P_0402_50V8J  [C_0402]  174.96 82.08 0 bottom
PC227  0.1U_0402_25V6-K  [C_0402]  143.47 70.42 270 bottom
PC228  2200P_0402_25V7-K  [C_0402]  172.35 84.92 270 bottom
PC229  2200P_0402_25V7-K  [C_0402]  146.49 88 270 bottom
PC230  2200P_0402_25V7-K  [C_0402]  174.99 75.75 270 top
PC231  2200P_0402_25V7-K  [C_0402]  144.36 69.51 90 bottom
PC301  0.1U_0402_10V6-K  [C_0402]  121.29 63.18 180 bottom
PC302  0.1U_0402_10V6-K  [C_0402]  120.4 64.05 0 bottom
PC303  0.1U_0402_6.3V7-K  [C_0402]  124.85 67.45 0 bottom
PC304  10U_0603_6.3V6M  [C_0603]  124.8 68.52 0 bottom
PC305  1U_0402_6.3V6-K  [C_0402]  126.73 66.94 0 bottom
PC306  0.1U_0402_25V6-K  [C_0402]  128 66.79 180 top
PC307  0.01U_0402_25V  [C_0402]  128.2 64.02 90 bottom
PC308  0.1U_0402_25V6  [C_0402]  120.89 58.25 90 bottom
PC309  10U_0805_25V6-K  [C_0805]  122.16 57.01 270 bottom
PC310  10U_0805_25V6-K  [C_0805]  120.38 57.04 270 bottom
PC311  0.1U_0603_25V7-M  [C_0603]  122.87 59.65 0 bottom
PC312  1U_0603_25V6-K  [C_0603]  127.85 61.24 90 bottom
PC313  680P_0402_50V7K  [C_0402]  118.47 51.6 0 bottom
PC314  330U_D2_2V_R9M  [C_D2]  105.85 53.25 90 bottom
PC316  2200P_0402_25V7-K  [C_0402]  106.31 50.61 180 bottom
PC317  0.1U_0402_25V6  [C_0402]  106.31 49.72 180 bottom
PC319  47P_0402_50V8-J  [C_0402]  120 58.28 90 bottom
PC320  68P_0402_50V8J  [C_0402]  121.78 58.25 90 bottom
PC321  2200P_0402_25V7-K  [C_0402]  123.45 57.16 270 bottom
PC401  0.1U_0201_6.3V6-K  [C_0201]  131.58 95.02 180 bottom
PC402  0.01U_0402_25V  [C_0402]  119.26 100.72 90 bottom
PC403  1U_0402_6.3V6-K  [C_0402]  121.6 102.04 180 bottom
PC404  1000P_0201_25V7-K  [C_0201]  128.77 101.44 180 bottom
